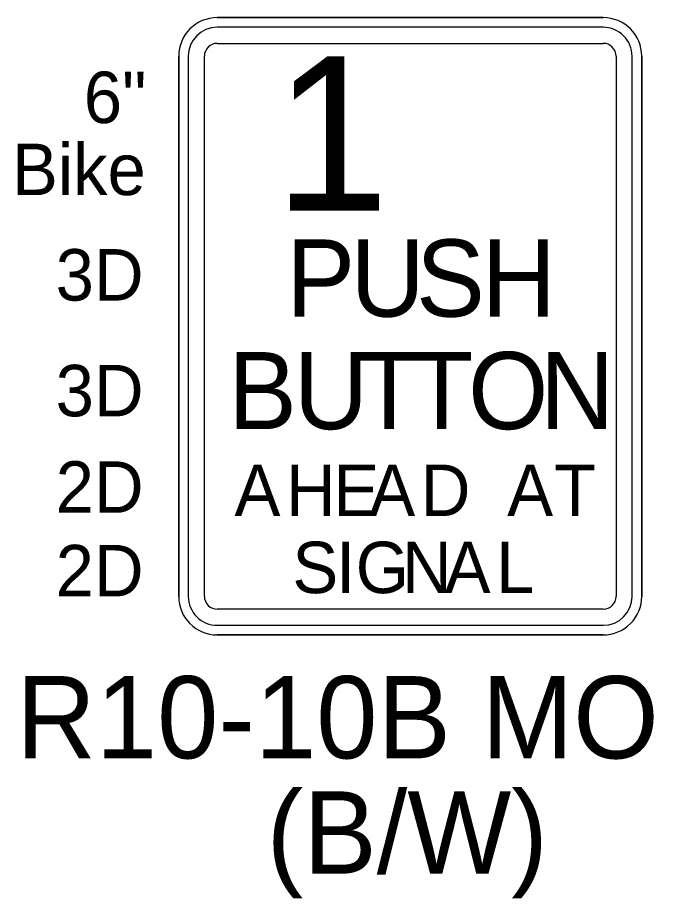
# Model space of a CAD drawing. Extents: x 99976 to 100136, y 99905 to 100011.
# Drawn here: x 100026.631 to 100027.191, y 99918.294 to 99919.065 of the extents above; entities that cross this region are included whole.
import ezdxf

# ---------------------------------------------------------------- set-up
doc = ezdxf.new("R2010")
doc.units = 0
doc.layers.add('TR_SN_ConstructionSigns', color=7, linetype='Continuous')

msp = doc.modelspace()

# ---------------------------------------------------------------- linework, layer by layer
at = {"layer": 'TR_SN_ConstructionSigns'}
for p, q in [((100026.80545, 99919.06451), (100027.14295, 99919.06451)), ((100027.14295, 99919.06451), (100026.80545, 99919.06451)), ((100027.14295, 99919.06451), (100026.80545, 99919.06451)), ((100027.14295, 99919.05607), (100026.80545, 99919.05607)), ((100026.80545, 99919.04201), (100027.14295, 99919.04201)), ((100026.7717, 99918.55826), (100026.7717, 99919.03076)), ((100026.7717, 99919.03076), (100026.7717, 99918.55826)), ((100026.7717, 99919.03076), (100026.7717, 99918.55826)), ((100026.78014, 99919.03076), (100026.78014, 99918.55826)), ((100026.7942, 99918.55826), (100026.7942, 99919.03076)), ((100027.1542, 99919.03076), (100027.1542, 99918.55826)), ((100027.16827, 99918.55826), (100027.16827, 99919.03076)), ((100027.1767, 99919.03076), (100027.1767, 99918.55826)), ((100027.1767, 99918.55826), (100027.1767, 99919.03076)), ((100027.1767, 99918.55826), (100027.1767, 99919.03076)), ((100027.14295, 99918.54701), (100026.80545, 99918.54701)), ((100026.80545, 99918.53295), (100027.14295, 99918.53295)), ((100027.14295, 99918.52451), (100026.80545, 99918.52451)), ((100026.80545, 99918.52451), (100027.14295, 99918.52451)), ((100026.80545, 99918.52451), (100027.14295, 99918.52451))]:
    msp.add_line(p, q, dxfattribs=at)
for centre, radius, start, end in [((100026.80545, 99919.03076), 0.03375, 90, 180), ((100026.80545, 99919.03076), 0.03375, 90, 180), ((100026.80545, 99919.03076), 0.03375, 90, 180), ((100027.14295, 99919.03076), 0.03375, 0.00001, 90.00001), ((100027.14295, 99919.03076), 0.03375, 0.00001, 90.00001), ((100027.14295, 99919.03076), 0.03375, 0.00001, 90.00001), ((100026.80545, 99919.03076), 0.02531, 90, 180), ((100027.14295, 99919.03076), 0.02531, 0, 90.00001), ((100026.80545, 99919.03076), 0.01125, 90, 180), ((100027.14295, 99919.03076), 0.01125, 0, 90.00001), ((100026.80545, 99918.55826), 0.03375, 180, 270), ((100026.80545, 99918.55826), 0.03375, 180, 270), ((100026.80545, 99918.55826), 0.03375, 180, 270), ((100026.80545, 99918.55826), 0.02531, 180, 270.00001), ((100026.80545, 99918.55826), 0.01125, 180, 270.00001), ((100027.14295, 99918.55826), 0.03375, 270, 0.00001), ((100027.14295, 99918.55826), 0.03375, 270, 0.00001), ((100027.14295, 99918.55826), 0.02531, 270.00001, 0), ((100027.14295, 99918.55826), 0.01125, 270.00001, 0), ((100027.14295, 99918.55826), 0.03375, 270, 0.00001)]:
    msp.add_arc(centre, radius, start, end, dxfattribs=at)

# ---------------------------------------------------------------- texts
for s, height, p in [('1', 0.135, (100026.85518, 99918.89576)), ('6"', 0.045, (100026.68872, 99918.97226)), ('Bike', 0.045, (100026.62591, 99918.90926)), ('S', 0.0675, (100026.97927, 99918.80295)), ('P', 0.0675, (100026.86587, 99918.80295)), ('U', 0.0675, (100026.92189, 99918.80295)), ('H', 0.0675, (100027.03664, 99918.80295)), ('3D', 0.045, (100026.66411, 99918.81701)), ('B', 0.0675, (100026.8149, 99918.70451)), ('U', 0.0675, (100026.87228, 99918.70451)), ('T', 0.0675, (100026.9283, 99918.70451)), ('T', 0.0675, (100026.9742, 99918.70451)), ('O', 0.0675, (100027.02483, 99918.70451)), ('N', 0.0675, (100027.0876, 99918.70451)), ('3D', 0.045, (100026.66411, 99918.71576)), ('2D', 0.045, (100026.66411, 99918.63139)), ('A', 0.045, (100026.82053, 99918.62857)), ('H', 0.045, (100026.86553, 99918.62857)), ('E', 0.045, (100026.90693, 99918.62857)), ('A', 0.045, (100026.93843, 99918.62857)), ('D', 0.045, (100026.98343, 99918.62857)), ('A', 0.045, (100027.05903, 99918.62857)), ('T', 0.045, (100027.09998, 99918.62857)), ('2D', 0.045, (100026.66411, 99918.55826)), ('S', 0.045, (100026.87115, 99918.56107)), ('I', 0.045, (100026.9094, 99918.56107)), ('G', 0.045, (100026.9265, 99918.56107)), ('N', 0.045, (100026.967, 99918.56107)), ('A', 0.045, (100027.00435, 99918.56107)), ('L', 0.045, (100027.04935, 99918.56107))]:
    msp.add_text(s, height=height, dxfattribs=at).set_placement(p)
for s, p in [('R10-10B MOD', (100026.6298, 99918.41651)), ('(B/W)', (100026.84863, 99918.31571))]:
    msp.add_text(s, height=0.072, rotation=360, dxfattribs=at).set_placement(p)

doc.saveas('drawing.dxf')
